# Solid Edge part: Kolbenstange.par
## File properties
Username: bmolnar
Dokumentum tartalom típus: 0
Author: bmolnar
Last saved by: bmolnar
Revision: 91
Sűrűség: 0,000 kg/m^3
Pontosság: 0,990
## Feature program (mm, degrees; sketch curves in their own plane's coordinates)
base feature "unnamed BaseFeature 1"
sketch for "unnamed Protrusion 1" plane through (0, 0, -20.6) normal (0, 0, -1) x-axis (0, 1, 0)
  circle centre (0, 0) radius 16
extrude "unnamed Protrusion 1" add finite 7.9 along +normal
thread "unnamed Thread 1"
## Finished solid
Body 1: solid body, 17 faces, 23 edges, 8 vertices.
  Faces by surface: plane 8, cylinder 4, torus 3, cone 2
  Edges by curve: circle 13, line 6, ellipse 2, intersection 2
Bounding box of the edges (mm; curved faces can reach further): 32.000 x 32.000 x 207.500, from (-16, -16, -28.5) to (16, 16, 179).
Cylindrical faces by radius (mm): R3.95 x1, R5 x1, R6 x1, R16 x1
Conical faces (half-angle, radius in mm at the cone's reference point): 20 deg R4.5 x1, 60 deg R4.575 x1
Toroidal faces (ring radius, tube radius in mm): R4.35 r0.4 x2, R4.8 r1.2 x1
Planar faces by outward normal: +x 1, +z 3, -x 1, -z 1, oblique 2
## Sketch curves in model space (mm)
circle centre (0, 0, -20.6) radius 16
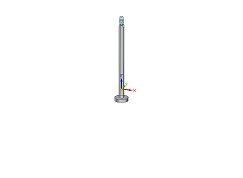
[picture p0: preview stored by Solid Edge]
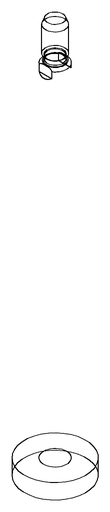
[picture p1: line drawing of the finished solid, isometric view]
